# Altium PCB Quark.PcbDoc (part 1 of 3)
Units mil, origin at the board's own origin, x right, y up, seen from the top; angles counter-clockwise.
Board outline 1220.47 x 944.88 mil, 6 copper layers (Top1, Signal2, Gnd3, Power4, Signal5, Bottom6), stack 32.534 mil thick; 106 components, 182 nets, 776 pads, 404 vias.
Unrouted connection lines stored in the file: 82.
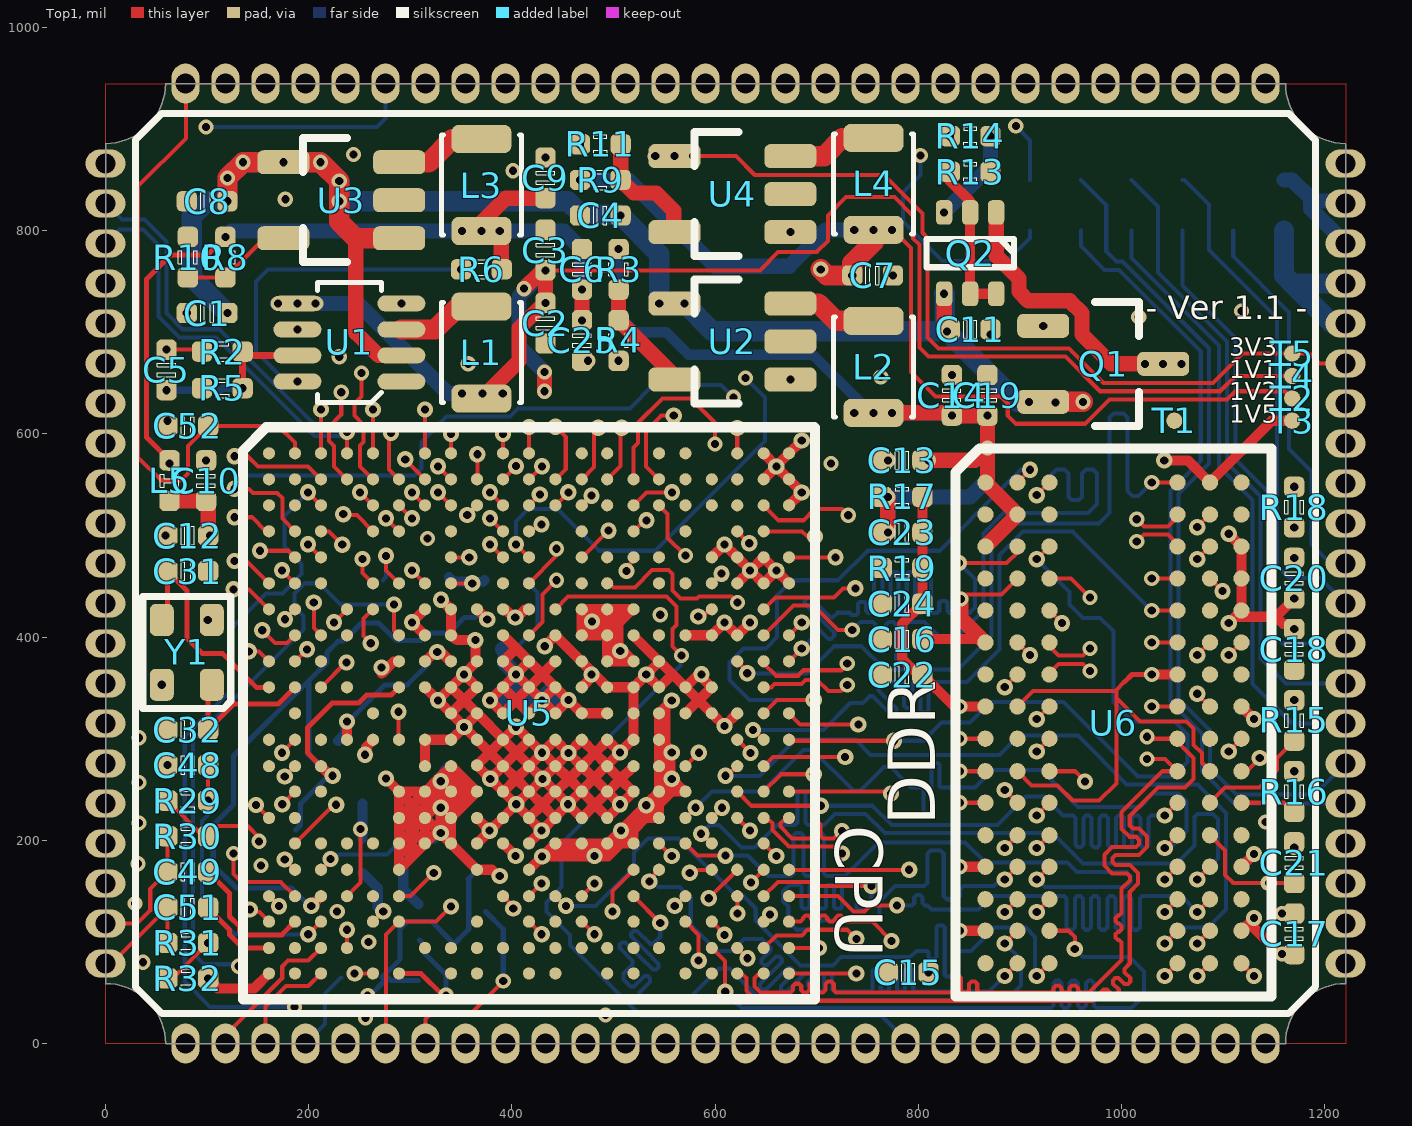
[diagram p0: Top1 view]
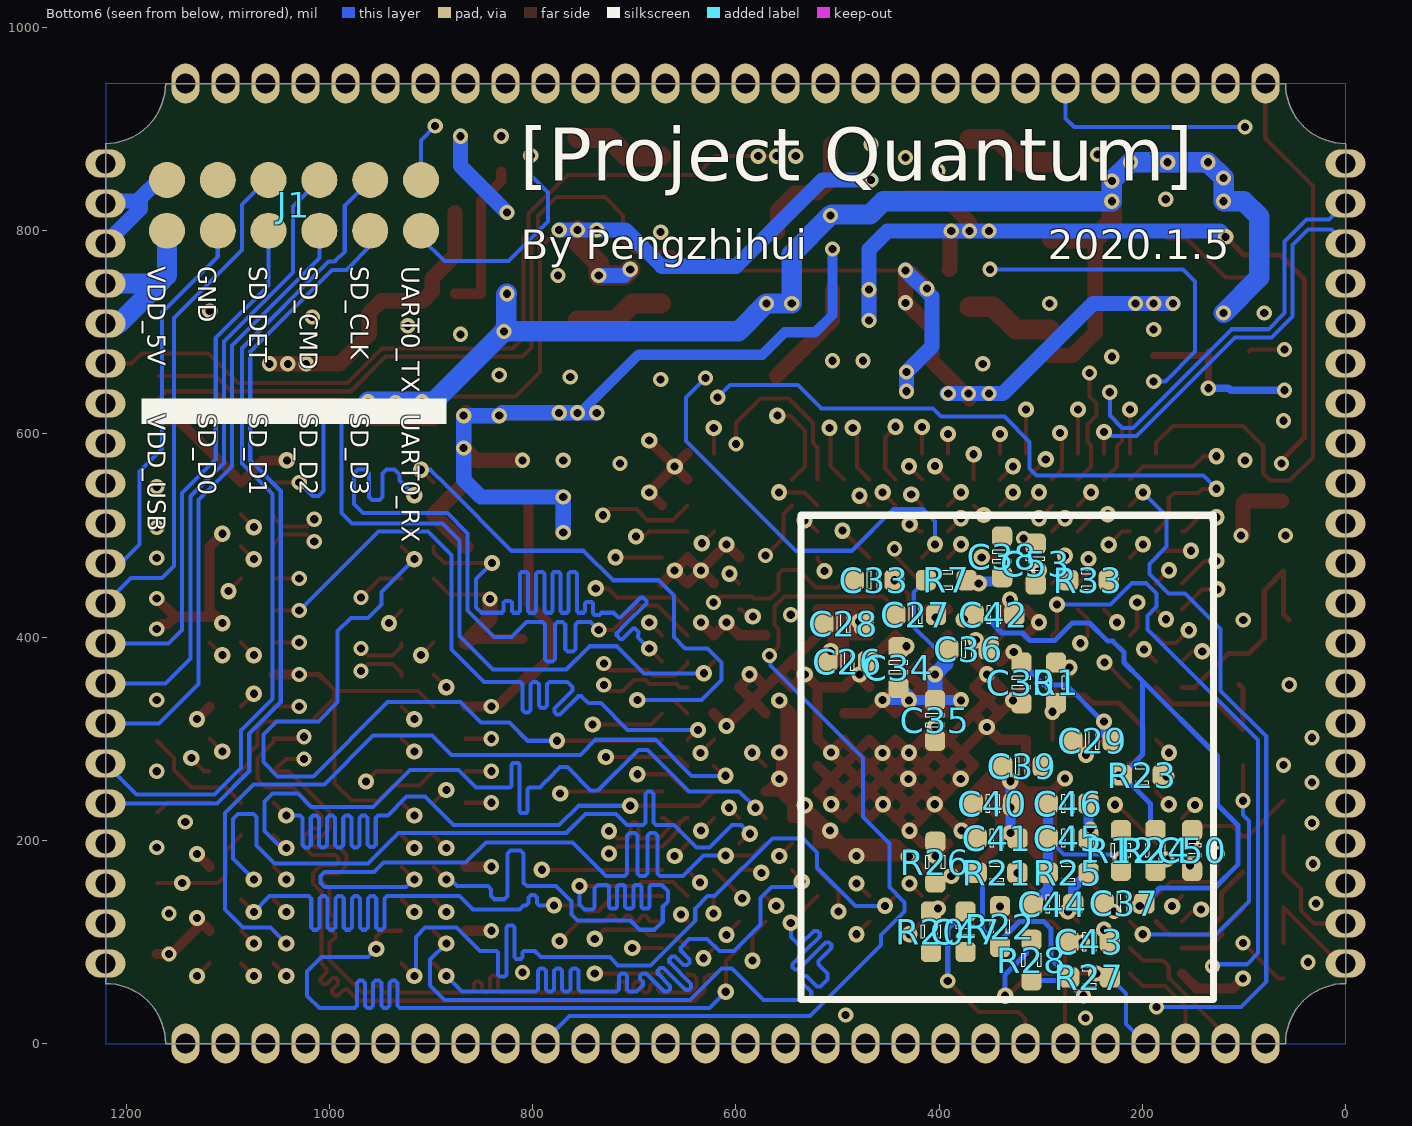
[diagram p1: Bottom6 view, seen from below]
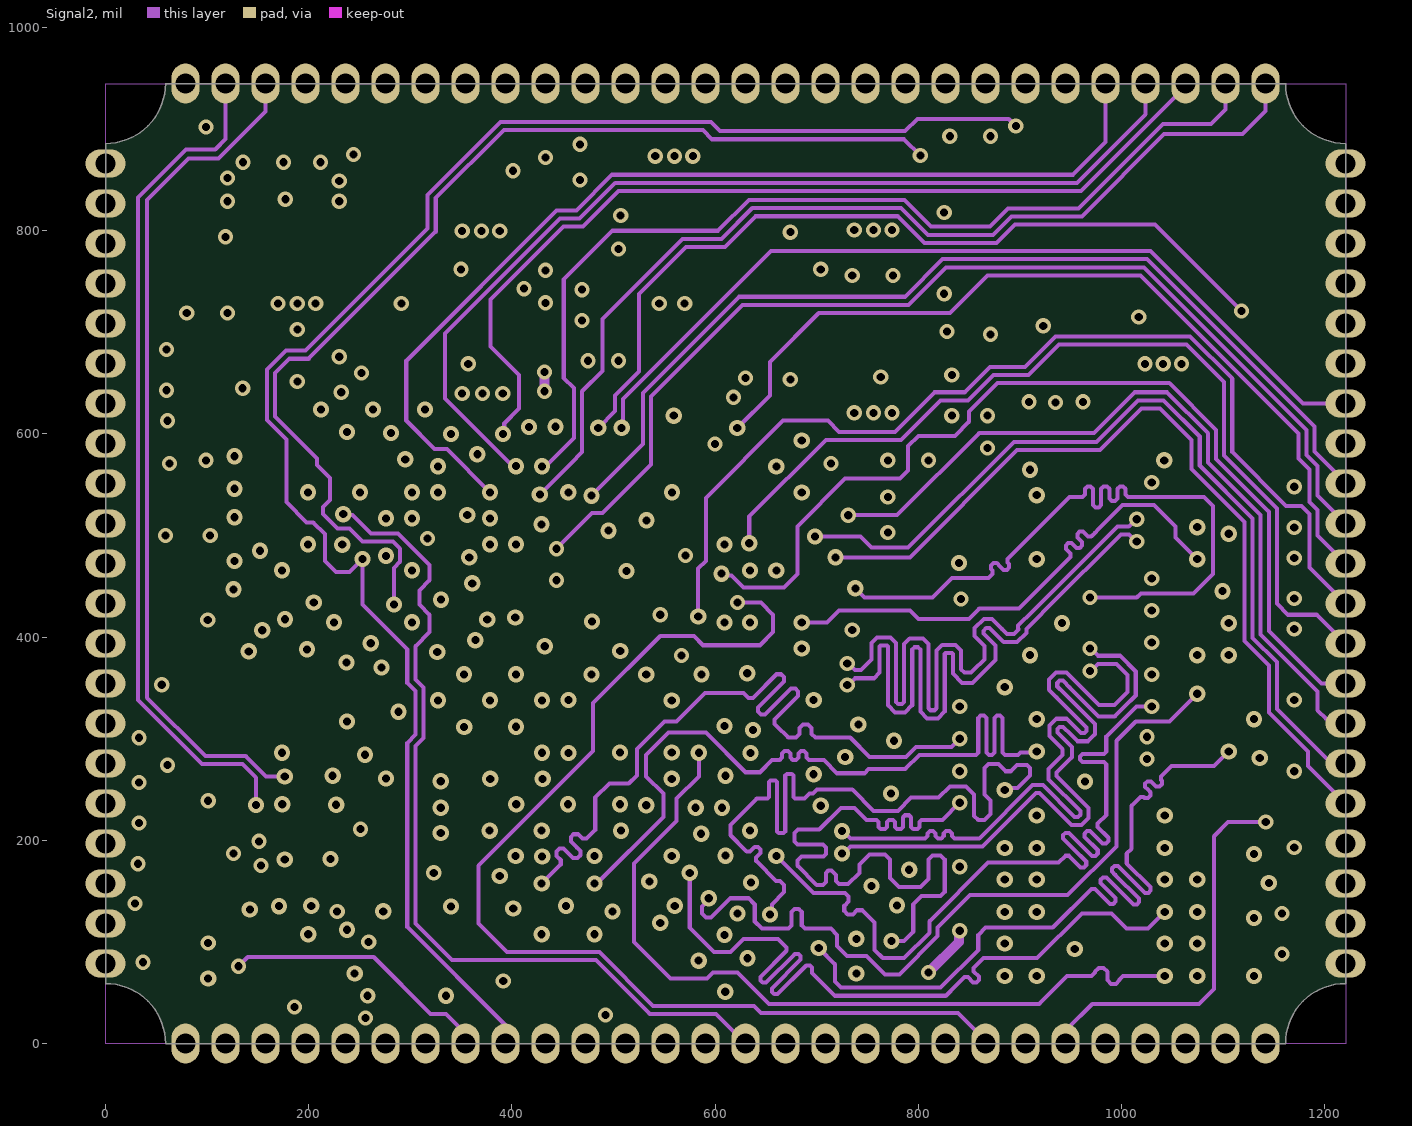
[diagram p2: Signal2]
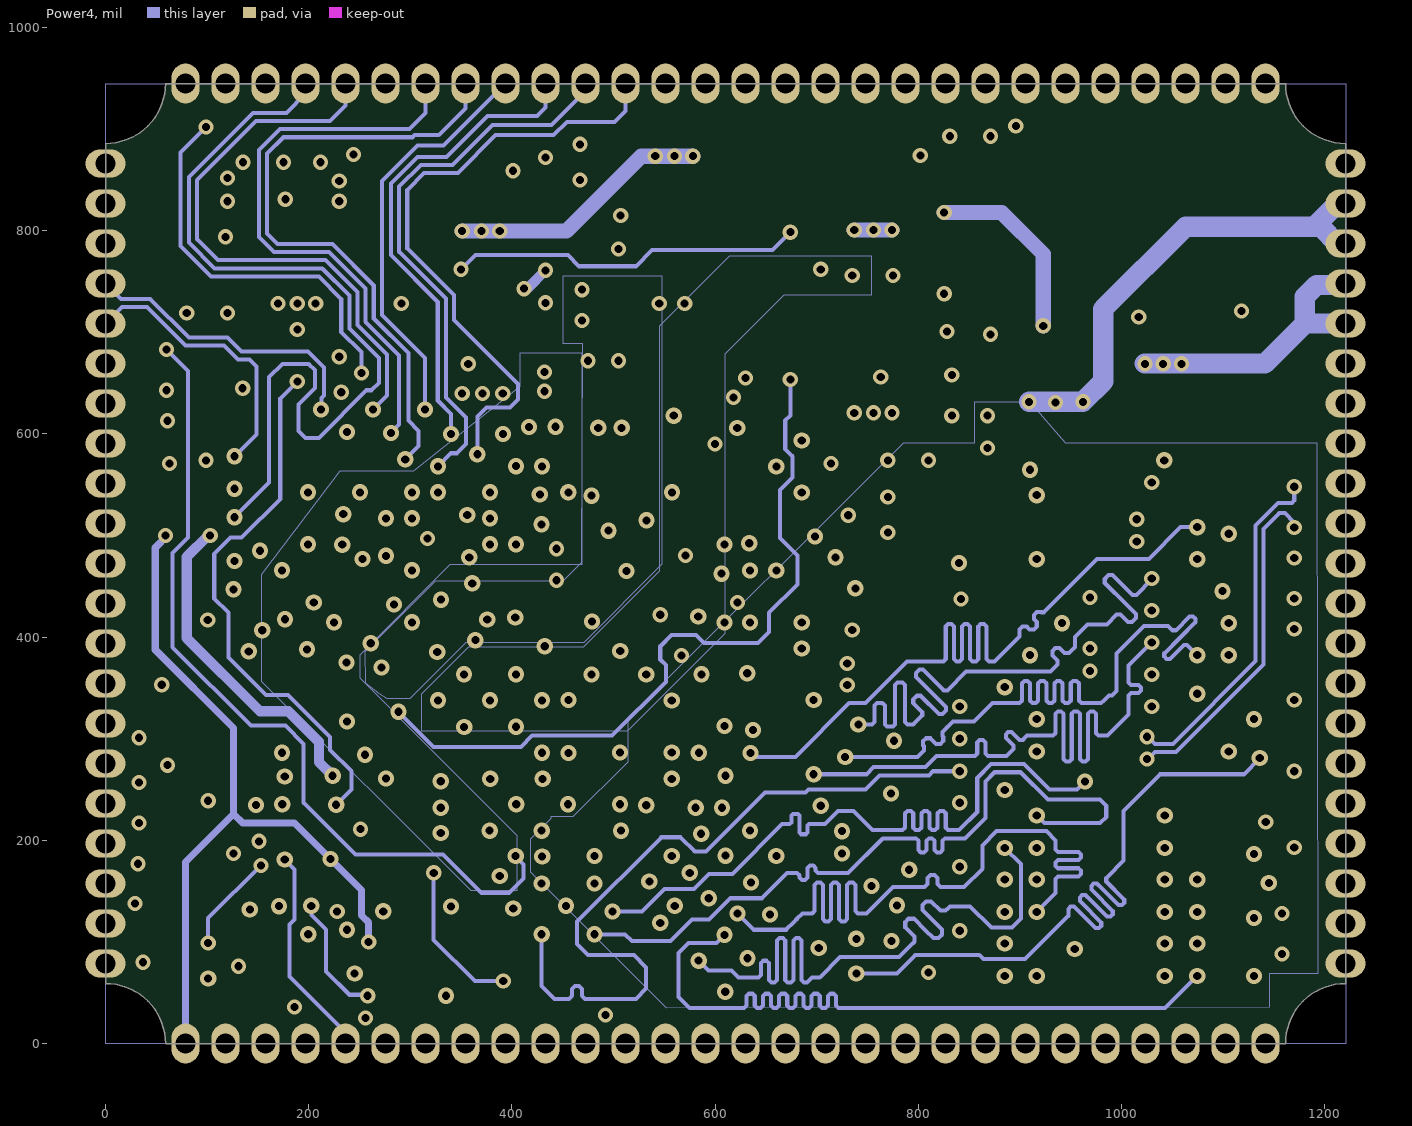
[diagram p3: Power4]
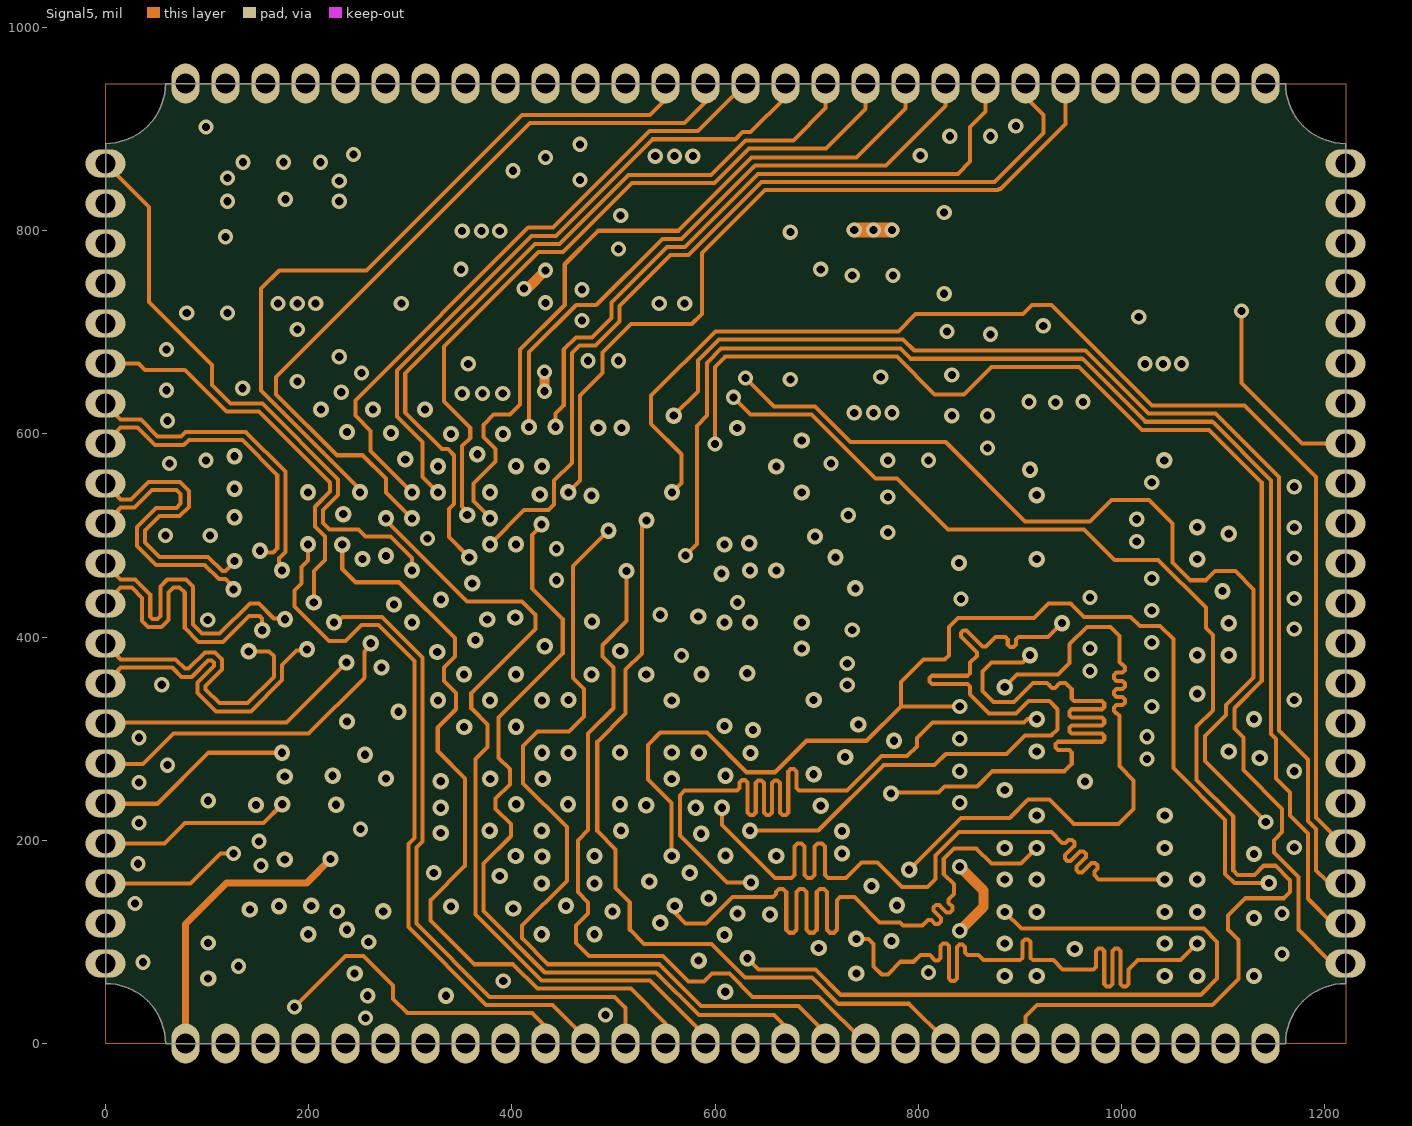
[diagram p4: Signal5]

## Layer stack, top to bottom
Top Solder: solder mask 0.8, Solder Resist, Dk 3.5
Top1: signal copper 1.378
Dielectric1: prepreg 4.2, PP-014, Dk 4.2
Signal2: signal copper 0.689
Dielectric3: core 5, Core-015, Dk 4.4
Gnd3: signal copper 0.689
Dielectric2: prepreg 8.6, PP-023, Dk 4.5
Power4: signal copper 0.689
Dielectric4: core 5, Core-015, Dk 4.4
Signal5: signal copper 0.689
Dielectric5: prepreg 4.2, PP-014, Dk 4.2
Bottom6: signal copper 1.4
Bottom Solder: solder mask 0.8, Solder Resist, Dk 3.5

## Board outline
0,59.06 0,885.83 ccw(c0,944.88) 59.06,944.88 1161.42,944.88 ccw(c1220.47,944.88) 1220.47,885.83 1220.47,59.06 ccw(c1220.47,0) 1161.42,0 59.06,0 ccw(c0,0)

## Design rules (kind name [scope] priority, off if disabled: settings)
AssemblyTestPointUsage [All] p0: scope1count=1 scope1_0_kind=Board scope1_0_value=Board scope2count=1 scope2_0_kind=Board scope2_0_value=Board commentlength=0
AssemblyTestpoint [All] p0: scope1count=1 scope1_0_kind=Board scope1_0_value=Board scope2count=1 scope2_0_kind=Board scope2_0_value=Board commentlength=0
Clearance [All] p0: scope1count=1 scope1_0_kind=Board scope1_0_value=Board scope2count=1 scope2_0_kind=Board scope2_0_value=Board commentlength=0 gap=4
Clearance [All] p1: gap=4 ignorepadtopadclearanceinfootprint=FALSE except(0: Arc-Hole Track-Hole SMDPad-Hole THPad-Hole Via-Hole Fill-Hole Poly-Hole Region-Hole Text-Hole)
ComponentClearance [All] p0: scope1count=1 scope1_0_kind=Board scope1_0_value=Board scope2count=1 scope2_0_kind=Board scope2_0_value=Board commentlength=0 gap=0 collisioncheckmode=3
ComponentClearance [All] p1: gap=0 collisioncheckmode=3 verticalgap=0 showdistances=FALSE
DiffPairsRouting [All] p0: scope1count=1 scope1_0_kind=Board scope1_0_value=Board scope2count=1 scope2_0_kind=Board scope2_0_value=Board commentlength=0
DiffPairsRouting [All] p1: maxlimit=4 minlimit=4 mostfreqgap=4 toplayer_minwidth=4 toplayer_maxwidth=4 toplayer_prefwidth=4 midlayer1_minwidth=4 midlayer1_maxwidth=4 midlayer1_prefwidth=4 midlayer2_minwidth=4 midlayer2_maxwidth=4 midlayer2_prefwidth=4 midlayer3_minwidth=4 midlayer3_maxwidth=4 midlayer3_prefwidth=4 midlayer4_minwidth=4 midlayer4_maxwidth=4 midlayer4_prefwidth=4 bottomlayer_minwidth=4 bottomlayer_maxwidth=4 bottomlayer_prefwidth=4 maxuncoupledlength=500
FabricationTestPointUsage [All] p0: scope1count=1 scope1_0_kind=Board scope1_0_value=Board scope2count=1 scope2_0_kind=Board scope2_0_value=Board commentlength=0 valid=0 allowmultiple=FALSE
FabricationTestpoint [All] p0: scope1count=1 scope1_0_kind=Board scope1_0_value=Board scope2count=1 scope2_0_kind=Board scope2_0_value=Board commentlength=0 side=3 testpointundercomponent=TRUE minsize=40 maxsize=100 preferedsize=60 minholesize=0 maxholesize=40 preferedholesize=32 testpointgrid=1
FanoutControl Fanout_Default [All] p0: scope1count=1 scope1_0_kind=Board scope1_0_value=Board scope2count=1 scope2_0_kind=Board scope2_0_value=Board commentlength=30 // Fanout_Default (Default Rule)
FanoutControl Fanout_Small [All] p0 off: scope1count=1 scope1_0_kind=Board scope1_0_value=Board scope2count=1 scope2_0_kind=Board scope2_0_value=Board commentlength=84 // Protel DXP Scope 1 Expression Was: (CompPinCount < 5)   Fanout_Small (Default Rule)
FanoutControl Fanout_SOIC [All] p0 off: scope1count=1 scope1_0_kind=Board scope1_0_value=Board scope2count=1 scope2_0_kind=Board scope2_0_value=Board commentlength=71 // Protel DXP Scope 1 Expression Was: IsSOIC   Fanout_SOIC (Default Rule)
FanoutControl Fanout_LCC [All] p0 off: scope1count=1 scope1_0_kind=Board scope1_0_value=Board scope2count=1 scope2_0_kind=Board scope2_0_value=Board commentlength=69 // Protel DXP Scope 1 Expression Was: IsLCC   Fanout_LCC (Default Rule)
FanoutControl Fanout_BGA [All] p0: scope1count=1 scope1_0_kind=Board scope1_0_value=Board scope2count=1 scope2_0_kind=Board scope2_0_value=Board commentlength=26 // Fanout_BGA (Default Rule)
FanoutControl Fanout_BGA [All] p1: bgadir=Out bgaviamode=Centered fanoutstyle=Auto fanoutdirection=Alternating viagrid=1 // Fanout_BGA (Default Rule)
Height [All] p0: scope1count=1 scope1_0_kind=Board scope1_0_value=Board scope2count=1 scope2_0_kind=Board scope2_0_value=Board commentlength=0
HoleSize [All] p0: scope1count=1 scope1_0_kind=Board scope1_0_value=Board scope2count=1 scope2_0_kind=Board scope2_0_value=Board commentlength=0 absolutevalues=TRUE maxlimit=10000 minlimit=8 maxpercent=80.000 minpercent=20.000
HoleSize [All] p1: absolutevalues=TRUE maxlimit=10000 minlimit=8 maxpercent=80.000 minpercent=20.000
HoleToHoleClearance [All] p0: scope1count=1 scope1_0_kind=Board scope1_0_value=Board scope2count=1 scope2_0_kind=Board scope2_0_value=Board commentlength=0
LayerPairs [All] p0: scope1count=1 scope1_0_kind=Board scope1_0_value=Board scope2count=1 scope2_0_kind=Board scope2_0_value=Board commentlength=0 enforce=TRUE
MinimumSolderMaskSliver [All] p0 off: scope1count=1 scope1_0_kind=Board scope1_0_value=Board scope2count=1 scope2_0_kind=Board scope2_0_value=Board commentlength=0
MinimumSolderMaskSliver [All] p1 off: minsoldermaskwidth=2
NetAntennae [All] p0: scope1count=1 scope1_0_kind=Board scope1_0_value=Board scope2count=1 scope2_0_kind=Board scope2_0_value=Board commentlength=0
PasteMaskExpansion [All] p0: scope1count=1 scope1_0_kind=Board scope1_0_value=Board scope2count=1 scope2_0_kind=Board scope2_0_value=Board commentlength=0 expansion=0
PlaneClearance [All] p0: scope1count=1 scope1_0_kind=Board scope1_0_value=Board scope2count=1 scope2_0_kind=Board scope2_0_value=Board commentlength=0 clearance=8
PlaneClearance [All] p1: clearance=8
PlaneConnect [All] p0: scope1count=1 scope1_0_kind=Board scope1_0_value=Board scope2count=1 scope2_0_kind=Board scope2_0_value=Board commentlength=0 planeconnectstyle=Direct reliefexpansion=20 reliefentries=4 reliefconductorwidth=10 reliefairgap=10
PlaneConnect [All] p1: planeconnectstyle=Direct reliefexpansion=20 reliefentries=4 reliefconductorwidth=10 reliefairgap=10
PolygonConnect [All] p0: scope1count=1 scope1_0_kind=Board scope1_0_value=Board scope2count=1 scope2_0_kind=Board scope2_0_value=Board commentlength=0 connectstyle=Direct reliefconductorwidth=10 reliefentries=4 polygonreliefangle="90 Angle"
PolygonConnect [All] p1: connectstyle=Direct reliefconductorwidth=10 reliefentries=4 polygonreliefangle="90 Angle" airgapwidth=10
RoutingCorners [All] p0: scope1count=1 scope1_0_kind=Board scope1_0_value=Board scope2count=1 scope2_0_kind=Board scope2_0_value=Board commentlength=0 cornerstyle=45-Degree minsetback=100 maxsetback=100
RoutingLayers [All] p0: scope1count=1 scope1_0_kind=Board scope1_0_value=Board scope2count=1 scope2_0_kind=Board scope2_0_value=Board commentlength=0 top layer=Automatic mid layer 1=Automatic mid layer 2=Automatic mid layer 3=Automatic mid layer 4=Automatic bottom layer=Automatic
RoutingPriority [All] p0: scope1count=1 scope1_0_kind=Board scope1_0_value=Board scope2count=1 scope2_0_kind=Board scope2_0_value=Board commentlength=0
RoutingTopology [All] p0: scope1count=1 scope1_0_kind=Board scope1_0_value=Board scope2count=1 scope2_0_kind=Board scope2_0_value=Board commentlength=0 topology=Shortest
RoutingVias [All] p0: scope1count=1 scope1_0_kind=Board scope1_0_value=Board scope2count=1 scope2_0_kind=Board scope2_0_value=Board commentlength=0 holewidth=8 width=16 viastyle="Through Hole" minholewidth=6 minwidth=12 maxholewidth=28 maxwidth=50
RoutingVias [All] p1: holewidth=8 width=16 viastyle="Through Hole" minholewidth=6 minwidth=12 maxholewidth=28 maxwidth=50
ShortCircuit [All] p0: scope1count=1 scope1_0_kind=Board scope1_0_value=Board scope2count=1 scope2_0_kind=Board scope2_0_value=Board commentlength=0 allowed=FALSE
SilkToBoardRegionClearance [All] p0: scope1count=1 scope1_0_kind=Board scope1_0_value=Board scope2count=1 scope2_0_kind=Board scope2_0_value=Board commentlength=0
SilkToSilkClearance [All] p0: scope1count=1 scope1_0_kind=Board scope1_0_value=Board scope2count=1 scope2_0_kind=Board scope2_0_value=Board commentlength=0
SilkToSilkClearance [All] p1: silktosilkclearance=0
SilkToSolderMaskClearance [All] p0 off: scope1count=1 scope1_0_kind=Board scope1_0_value=Board scope2count=1 scope2_0_kind=Board scope2_0_value=Board commentlength=44 // Protel DXP Scope 1 Expression Was: IsPad
SilkToSolderMaskClearance [IsPad] p1: minsilkscreentomaskgap=0 clearancetoexposedcopper=TRUE
SolderMaskExpansion [All] p0: scope1count=1 scope1_0_kind=Board scope1_0_value=Board scope2count=1 scope2_0_kind=Board scope2_0_value=Board commentlength=0 expansion=3
SolderMaskExpansion [All] p1: expansion=3 istentingtop=FALSE
UnRoutedNet [All] p0: scope1count=1 scope1_0_kind=Board scope1_0_value=Board scope2count=1 scope2_0_kind=Board scope2_0_value=Board commentlength=0
UnpouredPolygon [All] p0: scope1count=1 scope1_0_kind=Board scope1_0_value=Board scope2count=1 scope2_0_kind=Board scope2_0_value=Board commentlength=0
Width [All] p0: scope1count=1 scope1_0_kind=Board scope1_0_value=Board scope2count=1 scope2_0_kind=Board scope2_0_value=Board commentlength=0 maxlimit=10000 minlimit=4 preferedwidth=4
Width GND [All] p0 off: scope1count=1 scope1_0_kind=Board scope1_0_value=Board scope2count=1 scope2_0_kind=Board scope2_0_value=Board commentlength=70 maxlimit=50 minlimit=4 preferedwidth=10 // Protel DXP Scope 1 Expression Was: (InNet('AGND') OR InNet('GND'))
Width VCC [All] p0 off: scope1count=1 scope1_0_kind=Board scope1_0_value=Board scope2count=1 scope2_0_kind=Board scope2_0_value=Board commentlength=237 maxlimit=50 minlimit=4 preferedwidth=10 // Protel DXP Scope 1 Expression Was: (InNet('VDD_SYS_3.3V') OR InNet('VDD_AV_3.3V') OR InNet('VDD_5V') OR InNet('VDD1V2-SYS') OR InNet('VDD1V1-EPHY') OR InNet('VDD-CPUX') OR InNet('VDD-CPUS') OR InNet('VDD-CPUFB') OR InNet('VCC-DRAM'))
Width GND [(InNet('AGND') OR InNet('GND'))] p1: maxlimit=50 minlimit=4 preferedwidth=10
Width VCC [(InNet('VDD_SYS_3.3V') OR InNet('VDD_AV_3.3V') OR InNet('VDD_5V') OR InNet('VDD1V2-SYS') OR InNet('VDD1V1-EPHY') OR InNet('VDD-CPUX') OR InNet('VDD-CPUS') OR InNet('VDD-CPUFB') OR InNet('VCC-DRAM'))] p2: maxlimit=50 minlimit=4 preferedwidth=10
Width [All] p3: maxlimit=10000 minlimit=4 preferedwidth=4
21 further rules are at their usual default settings.

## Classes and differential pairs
component class Power: C1 C2 C3 C4 C5 C6 C7 C8 C9 C10 C11 C12 L1 L2 L3 L4 L5 Q1 Q2 R1 R2 R3 R4 R5 R6 R7 R8 R9 R10 R11 R12 R13 R14 T1 T2 T3 T4 T5 U1 U2 U3 U4
component class CPU&DRAM: C13 C14 C15 C16 C17 C18 C19 C20 C21 C22 C23 C24 C25 C26 C27 C28 C29 C30 C31 C32 C33 C34 C35 C36 C37 C38 C39 C40 C41 C42 C43 C44 C45 C46 C47 C48 C49 C50 C51 C52 C53 R15 R16 R17 R18 R19 R20 R21 R22 R23 R24 R25 R26 R27 R28 R29 R30 R31 R32 R33 R43 U5 U6 Y1
component class Connect: J1
differential pair SDQS0: +SDQS0_P -SDQS0_N
differential pair SDQS1: +SDQS1_P -SDQS1_N
differential pair SCK: +SCK_P -SCK_N
differential pair HTX0: +HTX0_P -HTX0_N
differential pair HTX1: +HTX1_P -HTX1_N
differential pair HTX2: +HTX2_P -HTX2_N
differential pair " ": +HTXC_P -HTXC_N

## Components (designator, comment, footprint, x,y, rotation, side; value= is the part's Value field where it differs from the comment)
C1 "10uF" CAP_0402 100,719 r0 top
C2 "10uF" CAP_0402 433,709 r90 top
C3 "0.1uF" CAP_0402 433,781 r270 top
C4 "10uF" CAP_0402 487,815 r0 top
C5 "10uF" CAP_0402 60,663 r90 top
C6 "10uF" CAP_0402 469,762 r270 top
C7 "10uF" CAP_0402 755,756 r180 top
C8 "10uF" CAP_0402 100,829 r0 top
C9 "10uF" CAP_0402 433,852 r270 top
C10 "10uF" CAP_0402 99,554 r270 top
C11 "10uF" CAP_0402 851,703 r180 top
C12 "10uF" CAP_0402 81,500 r0 top
C13 "10uF" CAP_0402 784,574 r0 top
C14 "1uF" CAP_0402 833,638 r270 top
C15 "0.1uF" CAP_0402 790,70 r0 top
C16 "0.1uF" CAP_0402 784,398 r0 top
C17 "0.1uF" CAP_0402 1170,108 r270 top
C18 "0.1uF" CAP_0402 1170,388 r90 top
C19 "0.1uF" CAP_0402 868,638 r270 top
C20 "0.1uF" CAP_0402 1170,458 r270 top
C21 "0.1uF" CAP_0402 1170,178 r270 top
C22 "0.1uF" CAP_0402 784,363 r0 top
C23 "0.1uF" CAP_0402 784,503 r180 top
C24 "0.1uF" CAP_0402 784,433 r0 top
C25 "0.1uF" CAP_0402 469,692 r90 top
C26 "0.1uF" CAP_0402 490,376 r0 bottom
C27 "0.1uF" CAP_0402 423,422 r180 bottom
C28 "0.1uF" CAP_0402 494,413 r180 bottom
C29 "1uF" CAP_0402 249,298 r180 bottom
C30 "0.1uF" CAP_0402 319,355 r90 bottom
C31 "18pF" CAP_0402 81,465 r0 top
C32 "18pF" CAP_0402 81,309 r0 top
C33 "10uF" CAP_0402 464,456 r0 bottom
C34 "0.1uF" CAP_0402 440,370 r270 bottom
C35 "0.1uF" CAP_0402 404,318 r90 bottom
C36 "0.1uF" CAP_0402 371,388 r0 bottom
C37 "0.1uF" CAP_0402 218,138 r0 bottom
C38 "0.1uF" CAP_0402 338,479 r270 bottom
C39 "10uF" CAP_0402 318,273 r0 bottom
C40 "0.1uF" CAP_0402 347,236 r180 bottom
C41 "0.1uF" CAP_0402 343,202 r180 bottom
C42 "0.1uF" CAP_0402 346,422 r0 bottom
C43 "1uF" CAP_0402 252,100 r0 bottom
C44 "10uF" CAP_0402 288,137 r180 bottom
C45 "10uF" CAP_0402 273,202 r180 bottom
C46 "0.1uF" CAP_0402 273,236 r180 bottom
C47 "0.1uF" CAP_0402 374,110 r90 bottom
C48 "1uF" CAP_0402 81,274 r180 top
C49 "0.1uF" CAP_0402 81,169 r180 top
C50 "10uF" CAP_0402 151,190 r90 bottom
C51 "0.1uF" CAP_0402 81,134 r180 top
C52 "0.1uF" CAP_0402 81,608 r0 top
C53 "0.1uF" CAP_0402 305,472 r270 bottom
J1 "MIPI0" TEST_CORE 910,800 r0 bottom
L1 "2.2uH" 2520-L 370,680 r270 top
L2 "2.2uH" 2520-L 756,666 r270 top
L3 "2.2uH" 2520-L 370,845 r270 top
L4 "2.2uH" 2520-L 756,846 r270 top
L5 "H0402" IND_0402 63,554 r270 top
Q1 "AO3415A" SOT23-3 982,669 r0 top
Q2 "BCM856BS" SOT363-6 851,778 r270 top
R1 "10K" RES_0402 285,355 r90 bottom
R2 "10K/1%" RES_0402 115,681 r180 top
R3 "15K/1%" RES_0402 505,762 r270 top
R4 "10K/1%" RES_0402 505,692 r90 top
R5 "12K/1%" RES_0402 115,645 r0 top
R6 "10K" RES_0402 370,762 r0 top
R7 "2R/1%" RES_0402 393,456 r180 bottom
R8 "30K/1%" RES_0402 118,774 r270 top
R9 "10K/1%" RES_0402 487,850 r180 top
R10 "6.8K/1%" RES_0402 81,774 r270 top
R11 "10K/1%" RES_0402 487,885 r0 top
R12 "0R" RES_0402 221,190 r90 bottom
R13 "10K/1%" RES_0402 851,858 r180 top
R14 "10K/1%" RES_0402 851,893 r180 top
R15 "240R/1%" RES_0402 1170,318 r90 top
R16 "240R/1%" RES_0402 1170,248 r90 top
R17 "2K/1%" RES_0402 784,538 r180 top
R18 "100R" RES_0402 1170,528 r90 top
R19 "2K/1%" RES_0402 784,468 r0 top
R20 "240R/1%" RES_0402 408,110 r270 bottom
R21 "1M" RES_0402 343,168 r0 bottom
R22 "10K" RES_0402 340,115 r270 bottom
R23 "47K" RES_0402 200,264 r0 bottom
R24 "10K" RES_0402 187,190 r90 bottom
R25 "220K/1%" RES_0402 273,168 r180 bottom
R26 "0R" RES_0402 403.68,178.5 r270 bottom
R27 "100K" RES_0402 252,65 r180 bottom
R28 "47K" RES_0402 309,82 r90 bottom
R29 "1K" RES_0402 81,239 r0 top
R30 "2K" RES_0402 81,204 r0 top
R31 "2K" RES_0402 81,99 r180 top
R32 "1K" RES_0402 81,64 r180 top
R33 "6K/1%" RES_0402 253,456 r0 bottom
T1 "测试点" TEST_PT 1052,613 r0 top
T2 "测试点" TEST_PT 1168.01,635 r90 top
T3 "测试点" TEST_PT 1168.01,613 r90 top
T4 "测试点" TEST_PT 1168.01,657 r90 top
T5 "测试点" TEST_PT 1168.01,679 r90 top
U1 "MP2143DJ" SOT23-8 240,690 r90 top
U2 "RT8059" SOT23-5 615,691 r180 top
U3 "RT8059" SOT23-5 230,830 r180 top
U4 "SY8089A" SOT23-5 615,836 r180 top
U5 "ALLWINNER-H3(FBGA-347)" "FBGA-347 - duplicate" 416.77,325 r0 top locked
U6 "K4B4G1646D-BCK0(FBGA-96_256Mx16_DDR3-1600_11-11-11)" FBGA96(HYNIX_SAMSUNG_512MX16_DDR3) 992,316 r270 top locked
Y1 "24MHz" 晶振2520 80,385 r90 top

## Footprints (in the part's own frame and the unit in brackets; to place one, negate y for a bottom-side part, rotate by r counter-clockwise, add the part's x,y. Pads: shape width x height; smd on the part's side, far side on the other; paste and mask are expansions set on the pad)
2520-L [mm]
  rrect50% 0.7x1.5 smd: 1(-1.15,0) 2(1.15,0)
  silkscreen extent -1.25,-1 1.25,1
CAP_0402 [mil]
  rrect50% 20x20 smd: 1(-20,0) 2(20,0)
  silkscreen extent -6,-9 6,9
FBGA96(HYNIX_SAMSUNG_512MX16_DDR3) [mil] "FBGA96(HYNIX_SAMSUNG_512MX16_DDR3)"
  rrect100% 16x16 smd: A1(-236.22,-125.98) A2(-236.22,-94.49) A3(-236.22,-62.99) A7(-236.22,63) A8(-236.22,95) A9(-236.22,126) B1(-204.72,-125.98) B2(-204.72,-94.49) B3(-204.72,-62.99) B7(-204.72,63) B8(-204.72,95) B9(-204.72,126) C1(-173.23,-125.98) C2(-173.23,-94.49) C3(-173.23,-62.99) C7(-173.23,63) C8(-173.23,95) C9(-173.23,126) D1(-141.73,-125.98) D2(-141.73,-94.49) D3(-141.73,-62.99) D7(-141.73,63) D8(-141.73,95) D9(-141.73,126) E1(-110.24,-125.98) E2(-110.24,-94.49) E3(-110.24,-62.99) E7(-110.24,63) E8(-110.24,95) E9(-110.24,126) F1(-78.74,-125.98) F2(-78.74,-94.49) F3(-78.74,-62.99) F7(-78.74,63) F8(-78.74,95) F9(-78.74,126) G1(-47.24,-125.98) G2(-47.24,-94.49) G3(-47.24,-62.99) G7(-47.24,63) G8(-47.24,95) G9(-47.24,126) H1(-15.75,-125.98) H2(-15.75,-94.49) H3(-15.75,-62.99) H7(-15.75,63) H8(-15.75,95) H9(-15.75,126) J1(16,-125.98) J2(16,-94.49) J3(16,-62.99) J7(16,63) J8(16,95) J9(16,126) K1(48,-125.98) K2(48,-94.49) K3(48,-62.99) K7(48,63) K8(48,95) K9(48,126) L1(79,-125.98) L2(79,-94.49) L3(79,-62.99) L7(79,63) L8(79,95) L9(79,126) M1(111,-125.98) M2(111,-94.49) M3(111,-62.99) M7(111,63) M8(111,95) M9(111,126) N1(142,-125.98) N2(142,-94.49) N3(142,-62.99) N7(142,63) N8(142,95) N9(142,126) P1(174,-125.98) P2(174,-94.49) P3(174,-62.99) P7(174,63) P8(174,95) P9(174,126) R1(205,-125.98) R2(205,-94.49) R3(205,-62.99) R7(205,63) R8(205,95) R9(205,126) T1(237,-125.98) T2(237,-94.49) T3(237,-62.99) T7(237,63) T8(237,95) T9(237,126)
  silkscreen extent -270,-156 270,156
"FBGA-347 - duplicate" [mil] "FBGA-347"
  rrect100% 12x12 smd: A1(-255.91,255.91) A2(-230.31,255.91) A3(-204.72,255.91) A4(-179.13,255.91) A5(-153.54,255.91) A7(-102.36,255.91) A8(-76.77,255.91) A10(-25.59,255.91) A11(0,255.91) A13(52,255.91) A14(77,255.91) A16(128,255.91) A17(154,255.91) A19(205,255.91) A20(231,255.91) A21(256,255.91) AA1(-255.91,-256) AA2(-230.31,-256) AA3(-204.72,-256) AA5(-153.54,-256) AA6(-127.95,-256) AA8(-76.77,-256) AA9(-51.18,-256) AA11(0,-256) AA12(26,-256) AA14(77,-256) AA15(103,-256) AA17(154,-256) AA18(180,-256) AA19(205,-256) AA20(231,-256) AA21(256,-256) B1(-255.91,230.32) B2(-230.31,230.32) B3(-204.72,230.32) B4(-179.13,230.32) B5(-153.54,230.32) B6(-127.95,230.32) B7(-102.36,230.32) B8(-76.77,230.32) B9(-51.18,230.32) B10(-25.59,230.32) B11(0,230.32) B12(26,230.32) B13(52,230.32) B14(77,230.32) B15(103,230.32) B16(128,230.32) B17(154,230.32) B18(180,230.32) B19(205,230.32) B20(231,230.32) B21(256,230.32) C1(-255.91,204.72) C2(-230.31,204.72) C3(-204.72,204.72) C5(-153.54,204.72) C6(-127.95,204.72) C7(-102.36,204.72) C8(-76.77,204.72) C9(-51.18,204.72) C10(-25.59,204.72) C11(0,204.72) C12(26,204.72) C13(52,204.72) C14(77,204.72) C15(103,204.72) C16(128,204.72) C17(154,204.72) C18(180,204.72) C19(205,204.72) C20(231,204.72) C21(256,204.72) D1(-255.91,179.13) D2(-230.31,179.13) D3(-204.72,179.13) D5(-153.54,179.13) D6(-127.95,179.13) D8(-76.77,179.13) D10(-25.59,179.13) D11(0,179.13) D13(52,179.13) D15(103,179.13) D17(154,179.13) D19(205,179.13) D20(231,179.13) E2(-230.31,153.54) E3(-204.72,153.54) E8(-76.77,153.54) E10(-25.59,153.54) E11(0,153.54) E13(52,153.54) E14(77,153.54) E15(103,153.54) E16(128,153.54) E18(180,153.54) E19(205,153.54) E20(231,153.54) E21(256,153.54) F1(-255.91,127.95) F2(-230.31,127.95) F3(-204.72,127.95) F5(-153.54,127.95) F6(-127.95,127.95) F7(-102.36,127.95) F8(-76.77,127.95) F10(-25.59,127.95) F11(0,127.95) F13(52,127.95) F14(77,127.95) F16(128,127.95) F17(154,127.95) F18(180,127.95) F19(205,127.95) F20(231,127.95) F21(256,127.95) G1(-255.91,102.36) G2(-230.31,102.36) G4(-179.13,102.36) G5(-153.54,102.36) G7(-102.36,102.36) G8(-76.77,102.36) G9(-51.18,102.36) G10(-25.59,102.36) G11(0,102.36) G12(26,102.36) G13(52,102.36) G14(77,102.36) G15(103,102.36) G18(180,102.36) G20(231,102.36) H2(-230.31,76.77) H3(-204.72,76.77) H4(-179.13,76.77) H6(-127.95,76.77) H7(-102.36,76.77) H8(-76.77,76.77) H10(-25.59,76.77) H11(0,76.77) H12(26,76.77) H13(52,76.77) H14(77,76.77) H15(103,76.77) H16(128,76.77) H17(154,76.77) H18(180,76.77) H19(205,76.77) H20(231,76.77) H21(256,76.77) J1(-255.91,51.18) J2(-230.31,51.18) J3(-204.72,51.18) J6(-127.95,51.18) J7(-102.36,51.18) J8(-76.77,51.18) J9(-51.18,51.18) J10(-25.59,51.18) J11(0,51.18) J12(26,51.18) J13(52,51.18) J14(77,51.18) J15(103,51.18) J16(128,51.18) J19(205,51.18) J20(231,51.18) J21(256,51.18) K1(-255.91,25.59) K2(-230.31,25.59) K3(-204.72,25.59) K4(-179.13,25.59) K6(-127.95,25.59) K7(-102.36,25.59) K8(-76.77,25.59) K9(-51.18,25.59) K10(-25.59,25.59) K11(0,25.59) K12(26,25.59) K13(52,25.59) K14(77,25.59) K15(103,25.59) K16(128,25.59) K17(154,25.59) K18(180,25.59) K20(231,25.59) L2(-230.31,0) L5(-153.54,0) L8(-76.77,0) L9(-51.18,0) L10(-25.59,0) L11(0,0) L12(26,0) L13(52,0) L14(77,0) L15(103,0) L16(128,0) L17(154,0) L18(180,0) L19(205,0) L20(231,0) L21(256,0) M1(-255.91,-26) M2(-230.31,-26) M3(-204.72,-26) M4(-179.13,-26) M5(-153.54,-26) M6(-127.95,-26) M7(-102.36,-26) M8(-76.77,-26) M9(-51.18,-26) M10(-25.59,-26) M11(0,-26) M12(26,-26) M13(52,-26) M14(77,-26) M15(103,-26) M16(128,-26) M19(205,-26) M20(231,-26) M21(256,-26) N1(-255.91,-52) N2(-230.31,-52) N3(-204.72,-52) N7(-102.36,-52) N8(-76.77,-52) N9(-51.18,-51.18) N10(-25.59,-52) N11(0,-52) N12(26,-52) N13(52,-52) N14(77,-52) N15(103,-52) N16(128,-52) N17(154,-52) N19(205,-52) N20(231,-52) P2(-230.31,-77) P3(-204.72,-77) P6(-127.95,-77) P7(-102.36,-77) P8(-76.77,-77) P9(-51.18,-77) P10(-25.59,-77) P11(0,-77) P12(26,-77) P13(52,-77) P14(77,-77) P15(103,-77) P16(128,-77) P17(154,-77) P19(205,-77) P20(231,-77) P21(256,-77) R1(-255.91,-103) R2(-230.31,-103) R6(-127.95,-103) R7(-102.36,-103) R8(-76.77,-103) R9(-51.18,-103) R10(-25.59,-103) R11(0,-103) R12(26,-103) R13(52,-103) R14(77,-103) R16(128,-103) R17(154,-103) R18(180,-103) R19(205,-103) R20(231,-103) R21(256,-103) T2(-230.31,-128) T3(-204.72,-128) T4(-179.13,-128) T5(-153.54,-128) T6(-127.95,-128) T7(-102.36,-128) T8(-76.77,-128) T9(-51.18,-128) T10(-25.59,-128) T11(0,-128) T12(26,-128) T13(52,-128) T14(77,-128) T15(103,-128) T16(128,-128) T17(154,-128) T18(180,-128) T20(231,-128) U2(-230.31,-154) U3(-204.72,-154) U4(-179.13,-154) U6(-127.95,-154) U9(-51.18,-154) U11(0,-154) U15(103,-154) U16(128,-154) U18(180,-154) U19(205,-154) U20(231,-154) U21(256,-154) V1(-255.91,-180) V2(-230.31,-180) V3(-204.72,-180) V4(-179.13,-180) V5(-153.54,-180) V6(-127.95,-180) V10(-25.59,-180) V11(0,-180) V12(26,-180) V13(52,-180) V15(103,-180) V17(154,-180) V19(205,-180) V20(231,-180) V21(256,-180) W1(-255.91,-205) W2(-230.31,-205) W3(-204.72,-205) W5(-153.54,-205) W6(-127.95,-205) W9(-51.18,-205) W11(0,-205) W12(26,-205) W13(52,-205) W15(103,-205) W17(154,-205) W18(180,-205) W20(231,-205) W21(256,-205) Y1(-255.91,-231) Y2(-230.31,-231) Y3(-204.72,-231) Y4(-179.13,-231) Y7(-102.36,-231) Y8(-76.77,-231) Y9(-51.18,-231) Y10(-25.59,-231) Y11(0,-231) Y12(26,-231) Y13(52,-231) Y14(77,-231) Y15(103,-231) Y16(128,-231) Y17(154,-231) Y18(180,-231) Y19(205,-231) Y20(231,-231) Y21(256,-231)
  silkscreen extent -281,-281 281,281
IND_0402 [mil]
  rrect50% 20x20 smd: 1(-20,0) 2(20,0)
  silkscreen extent -7,-9 7,9
RES_0402 [mil]
  rrect50% 20x20 smd: 1(-20,0) 2(20,0)
  silkscreen extent -7,-10 7,10
SOT23-3 [mm] "SOT23, 3-Leads, Body 3.1x3.0mm (max), Pitch 0.95mm, IPC Medium Density"
  rrect50% 1.3x0.6 smd: 1(-1.5,0.95) 2(-1.5,-0.95) 3(1.5,0)
  silkscreen extent -0.2,-1.55 0.9,1.55
SOT23-5 [mm] "SOT23, 3-Leads, Body 3.1x3.0mm (max), Pitch 0.95mm, IPC Medium Density"
  rrect50% 1.3x0.6 smd: 1(-1.5,0.95) 2(-1.5,0) 3(-1.5,-0.95) 4(1.396,-0.95) 5(1.396,0.95)
  silkscreen extent -0.2,-1.55 0.9,1.55
SOT23-8 [mm]
  oval 0.4x1.2 smd: 1(-0.975,-1.3) 2(-0.325,-1.3) 3(0.325,-1.3) 4(0.975,-1.3) 5(0.975,1.3) 6(0.325,1.3) 7(-0.325,1.3) 8(-0.975,1.3)
  silkscreen extent -1.5,-0.8 1.5,0.8
SOT363-6 [mil]
  rrect50% 24x16 smd: 1(-40,25.59) 2(-40,0) 3(-40,-25.59) 4(40,-25.59) 5(40,0) 6(40,25.59)
  silkscreen extent -14,-43 14,43
TEST_CORE [mm]
  round 0.9 smd: 1(0,0) 2(0,-1.27) 3(1.27,0) 4(1.27,-1.27) 5(2.54,0) 6(2.54,-1.27) 7(3.81,0) 8(3.81,-1.27) 9(5.08,0) 10(5.08,-1.27) 11(6.35,0) 12(6.35,-1.27)
TEST_PT [mil]
  rrect100% 16x16 smd: 0(0,0.01)
晶振2520 [mm]
  rrect50% 0.8x0.6 smd: 1(-0.81,-0.625) 2(0.81,-0.625) 3(0.81,0.625) 4(-0.81,0.625)
  silkscreen extent -1.4,-1.1 1.4,1.1

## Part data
C1 C2 C3 C4 C5 C6 C7 C8 C9 C10 C11 C12 C13 C14 C15 C16 C17 C18 C19 C20 C21 C22 C23 C24 C25 C26 C27 C28 C29 C30 C31 C32 C33 C34 C35 C36 C37 C38 C39 C40 C41 C42 C43 C44 C45 C46 C47 C48 C49 C50 C51 C52 C53: library part 电容-0402, "Capacitor"
J1: library part TEST_12P
L1 L2 L3 L4: library part 电感-2520, "磁珠"
L5: library part Ind_0402, "Inductor"
Q1: "MOSFET"
Q2: "Transistor"
R1 R2 R3 R4 R5 R6 R7 R8 R9 R10 R11 R12 R13 R14 R15 R16 R17 R18 R19 R20 R21 R22 R23 R24 R25 R26 R27 R28 R29 R30 R31 R32 R33: library part 电阻-0402, "Resistor"
U1 U2 U3 U4: "LDO"
U6: library part K4B8G1646Q-MYK0(FBGA-96_512MX16_DDR3-1600)
Y1: library part 晶振-4Pin-无源, "2520无源"

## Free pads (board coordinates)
  oval 39.37x27.56 hole 19.68: 1(0,866.14) 2(0,826.77) 3(0,787.4) 4(0,748.03) 5(0,708.66) 6(0,669.29) 7(0,629.92) 8(0,590.55) 9(0,551.18) 10(0,511.81) 11(0,472.44) 12(0,433.07) 13(0,393.7) 14(0,354.33) 15(0,314.96) 16(0,275.59) 17(0,236.22) 18(0,196.85) 19(0,157.48) 20(0,118.11) 21(0,78.74) 50(1220.47,78.74) 51(1220.47,118.11) 52(1220.47,157.48) 53(1220.47,196.85) 54(1220.47,236.22) 55(1220.47,275.59) 56(1220.47,314.96) 57(1220.47,354.33) 58(1220.47,393.7) 59(1220.47,433.07) 60(1220.47,472.44) 61(1220.47,511.81) 62(1220.47,551.18) 63(1220.47,590.55) 64(1220.47,629.92) 65(1220.47,669.29) 66(1220.47,708.66) 67(1220.47,748.03) 68(1220.47,787.4) 69(1220.47,826.77) 70(1220.47,866.14)
  oval 27.56x39.37 hole 19.68: 22(78.74,0) 23(118.11,0) 24(157.48,0) 25(196.85,0) 26(236.22,0) 27(275.59,0) 28(314.96,0) 29(354.33,0) 30(393.7,0) 31(433.07,0) 32(472.44,0) 33(511.81,0) 34(551.18,0) 35(590.55,0) 36(629.92,0) 37(669.29,0) 38(708.66,0) 39(748.03,0) 40(787.4,0) 41(826.77,0) 42(866.14,0) 43(905.51,0) 44(944.88,0) 45(984.25,0) 46(1023.62,0) 47(1062.99,0) 48(1102.36,0) 49(1141.73,0) 71(1141.73,944.88) 72(1102.36,944.88) 73(1062.99,944.88) 74(1023.62,944.88) 75(984.25,944.88) 76(944.88,944.88) 77(905.51,944.88) 78(866.14,944.88) 79(826.77,944.88) 80(787.4,944.88) 81(748.03,944.88) 82(708.66,944.88) 83(669.29,944.88) 84(629.92,944.88) 85(590.55,944.88) 86(551.18,944.88) 87(511.81,944.88) 88(472.44,944.88) 89(433.07,944.88) 90(393.7,944.88) 91(354.33,944.88) 92(314.96,944.88) 93(275.59,944.88) 94(236.22,944.88) 95(196.85,944.88) 96(157.48,944.88) 97(118.11,944.88) 98(78.74,944.88)

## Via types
v1: diameter 16, hole 8, Top1 to Bottom6, tented both sides, 238 vias
v2: diameter 15, hole 8, Top1 to Bottom6, tented both sides, 166 vias

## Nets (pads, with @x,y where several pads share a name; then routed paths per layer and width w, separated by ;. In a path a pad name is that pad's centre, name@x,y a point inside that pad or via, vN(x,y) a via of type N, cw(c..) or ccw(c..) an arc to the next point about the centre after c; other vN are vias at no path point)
AGND: C12.1 C43.2 C44.1 C45.1 C46.1 pad.22 R12.1 R25.1 U5.U3 | length 1257.2
  Top1 w4: U5.U3@212.05,171 v1@224.55,183.5
  Signal5 w7: pad.22@78.74,0 78.74,117.74 119,158 198.05,158 v1(221.55,181.5)
  Power4 w7: v2@61,500 49,488 49,387.57 126,310.57 126,226 ; pad.22@78.74,0 78.74,178.74 126,226 ; v2(259,100) 259,119 252,126 252,151.05 v1(221.55,181.5) 186.05,217 135,217 126,226
  Bottom6 w4: v1(221.55,181.5) 224.79,181.5 229.29,186 277,186 C45.1@293,202
  Bottom6 w10: C46.1@293,236 C45.1@293,202 R25.1@293,168 293,152 C44.1@308,137
  other v2: 59,500
AP-RESET#: C47.2 pad.28 R21.1 U5.V6 | length 386.8
  Top1 w4: U5.V6@288.82,145 300,145 v2(323,168) ; pad.28@314.96,0 314.96,23.96 322,31 361,31 v2(391.5,61.5)
  Power4 w4: v2(323,168) 323,102 363.5,61.5 v2(391.5,61.5)
  Bottom6 w5: C47.2@374,130 391.5,112.5 v2(391.5,61.5)
CAM_D0: pad.81 U5.C9 | length 732.4
  Top1 w4: v1(356,520.13) U5.C9@365.59,529.72
  Signal5 w4: v1(356,520.13) 356,523.38 351,528.38 351,588 359,596 359,606 333,632 333,686 426,779 450.19,779 518.19,847 599.43,847 633.43,881 709,881 748.03,920.03 pad.81@748.03,944.88
CAM_D1: pad.77 U5.E10 | length 872.6
  Top1 w4: v1(378.39,491.34) U5.E10@391.18,478.54
  Signal5 w4: v1(378.39,491.34) 412.05,525 436,525 441.46,530.46 441.46,554 459,571.54 459,679.69 466.31,687 482.31,687 506,710.69 506,726 556,776 573.69,776 609.69,812 644.19,846.5 645.69,848 724.46,848 748.94,848 771.63,848 842.31,848 875,848 923,896 923,914 905.51,931.49 pad.77@905.51,944.88
CAM_D2: pad.80 U5.D10 | length 755
  Top1 w4: v1(378.39,516.93) U5.D10@391.18,504.13
  Signal5 w4: v1(378.39,516.93) 378.39,517.55 362,533.93 362,551 384,573 384,585 372,597 372,609 382,619 398,619 408,629 408,683 452,727 452,767 485,800 563.75,800 599.75,836 635.75,872 739,872 787.4,920.4 pad.80@787.4,944.88
CAM_D3: pad.83 U5.C8 | length 662
  Top1 w4: v1(327.2,542.52) U5.C8@340,529.72
  Signal5 w4: v1(327.2,542.52) 312,557.72 312,592 287,617 287,662.63 419.37,795 443.56,795 538.56,890 619.8,890 625.8,896 626.8,897 635,897 669.29,931.29 pad.83@669.29,944.88
CAM_D4: pad.71 U5.C11 | length 999.6
  Top1 w4: U5.C11@416.77,529.72 v1(427.46,540.41)
  Signal2 w4: v1(427.46,540.41) 458.05,571 ; 458.05,571.05 469,582 469,642 489,662 489,713 568,792 606.31,792 636.54,822.22 783.09,822.22 809.31,796 873.69,796 891.69,814 961,814 1042,895 1070,895 1119,895 1141.73,917.73 pad.71@1141.73,944.88
CAM_D5: pad.76 U5.C12 | length 793.6
  Top1 w4: U5.C12@442.77,529.72 v1(455.57,542.52)
  Signal5 w4: v1(455.57,542.52) 467,553.95 467,638 489,660 489,680 517,708 577,708 587,718 587,778 613,804 649,840 727.77,840 752.25,840 774.94,840 845.63,840 878.31,840 879.31,841 881,841 944.88,904.88 pad.76@944.88,944.88
CAM_D6: pad.82 U5.E8 | length 778.7
  Top1 w4: U5.E8@340,478.54 350.83,478.54 v1(358,478.54)
  Signal5 w4: v1(358,478.54) 338,498.54 338,526 343,531 343,579 337,585 331,585 295,621 295,659.31 422.69,787 446.88,787 513.88,854 514.88,855 596.12,855 627.62,886.5 630.12,889 677,889 708.66,920.66 pad.82@708.66,944.88
CAM_D7: pad.79 U5.A11 | length 632
  Top1 w4: U5.A11@416.77,580.91 v1(416.77,606.91)
  Signal5 w4: v1(416.77,606.91) 416.77,680.46 463.31,727 483,727 548,792 567.06,792 603.06,828 637.56,862.5 639.06,864 717.83,864 742.31,864 768,864 826.77,922.77 pad.79@826.77,944.88
CAM_HSYNC: pad.72 U5.B11 | length 989.2
  Top1 w4: U5.B11@416.77,555.32 v1(429.57,568.11)
  Signal2 w4: v1(429.57,568.11) 433.11,568.11 461,596 461,645 451,655 451,752 499,800 603,800 633.22,830.22 786.4,830.22 812.63,804 870.37,804 888.37,822 957.69,822 1040.69,905 1088,905 1102.36,919.36 pad.72@1102.36,944.88
CAM_MCLK: pad.73 U5.A10 | length 943.3
  Top1 w4: U5.A10@391.18,580.91 v1(391.18,599.91)
  Signal2 w4: v1(391.18,599.91) 392.44,601.17 392.44,610.44 407,625 407,658 379,686 379,732.37 450.63,804 470,804 505,839 891,839 960,839 1062.99,941.99 pad.73@1062.99,944.88
CAM_PCLK: pad.74 U5.B10 | length 988.9
  Top1 w4: U5.B10@391.18,555.32 403.98,568.11 v1(403.98,568.25)
  Signal2 w4: 396.94,572.03 400.73,568.25 v1(403.98,568.25) ; 396.94,572.06 334,635 334,698.69 447.31,812 466.69,812 501.69,847 886,847 956,847 1023.62,914.62 pad.74@1023.62,944.88
CAM_VSYNC: pad.75 U5.C10 | length 1023.7
  Top1 w4: v1(378.39,542.52) U5.C10@391.18,529.72
  Signal2 w4: v1(378.39,542.52) 335.91,585 324,585 296,613 296,672 444,820 463.37,820 498.49,855.12 878.12,855.12 952.12,855.12 984.25,887.25 pad.75@984.25,944.88
EPHY-LINK-LED: C52.2 pad.98 U5.A2 | length 606.7
  Top1 w4: pad.98@79,944.62 79,891 32,844 32,577 55,554 74,554 81,561 81,588 C52.2@101,608 170,608 186.46,591.54 U5.A2@186.46,580.91
EPHY-RXN: pad.3 U5.A4 | length 391.2
  Top1 w4: U5.A4@237.64,580.91 v1(237.64,601.91)
  Bottom6 w4: pad.3@0,787.4 13.6,801 37,801 52,786 52,715.69 72.69,695 108.69,695 205.69,598 230.49,598 234.39,601.91 v1(237.64,601.91)
EPHY-RXP: pad.2 U5.B4 | length 490.8
  Top1 w4: v2(232,641) 232,619 220,607 220,593 224.84,588.16 224.84,568.11 U5.B4@237.64,555.32
  Bottom6 w4: pad.2@0,826.77 0.23,827 16.11,811.11 38.2,811.11 60,789.31 60,719 76,703 112,703 209,606 220,606 232,618 v2(232,641)
EPHY-SPD-LED: C53.2 pad.1 U5.F7 | length 605.5
  Top1 w4: v1(301.61,465.75) U5.F7@314.41,452.95
  Signal5 w4: pad.1@0,866.14 43,823.14 43,730 105,668 105,648 123,630 154.31,630 229,555.31 229,540 214,525 214,512.31 220.31,506 249,506 256,499 280.69,499 301.61,478.07 v1(301.61,465.75)
EPHY-TXN: pad.4 U5.A3 | length 334.9
  Top1 w4: U5.A3@212.05,580.91 U5.A3@212.05,580.91 212,623.95 v1(212.05,624)
  Power4 w4: pad.4@0,748.03 15.03,733 44,733 82,695 120,695 133.81,681.19 199.13,681.19 215,665.31 215,638 212.42,635.42 212.42,624.38 v1(212.05,624)
EPHY-TXP: pad.5 U5.B3 | length 371.3
  Top1 w4: v1(127,578) 140,578 150,568 199.36,568 U5.B3@212.05,555.32
  Power4 w4: pad.5@0,708.66 16.34,725 40.69,725 78.69,687 116.69,687 130.5,673.19 141.81,673.19 148.5,666.5 148.5,599.5 v1(127,578)
GND: C1.1 C2.1 C3.1 C4.1 C6.1 C7.1 C8.1 C9.1 C10.1 C11.1 C13.1 C14.1 C15.1 C16.1 C17.1 C18.1 C19.1 C20.1 C21.1 C22.1 C24.1 C25.1 C26.1 C27.1 C28.1 C29.1 C30.1 C31.2 C32.1 C33.2 C34.1 C35.1 C36.1 C37.2 C38.1 C39.1 C40.1 C41.1 C42.1 C47.1 C48.2 C52.1 C53.1 J1.10 pad.45 pad.46 pad.47 pad.48 pad.49 pad.70 R4.1 R5.1 R10.1 R11.1 R12.2 R13.1 R14.2 R15.2 R16.2 R19.1 R20.2 R32.1 R33.1 T1.0 U1.4 U1.6 U2.2 U3.2 U4.2 U5.A20 U5.A21 U5.AA1 U5.B20 U5.B21 U5.C21 U5.E18 U5.E19 U5.E20 U5.F19 U5.F20 U5.F21 U5.G8 U5.H8 U5.H12 U5.H15 U5.H17 U5.H18 U5.H19 U5.J9 U5.J13 U5.J16 U5.K7 U5.K8 U5.K9 U5.K13 U5.K14 U5.K15 U5.K16 U5.K17 U5.K18 U5.L8 U5.L9 U5.L15 U5.L17 U5.L18 U5.L19 U5.M5 U5.M7 U5.M8 U5.M9 U5.M10 U5.M11 U5.M12 U5.M13 U5.M14 U5.M15 U5.N7 U5.N9 U5.N10 U5.N11 U5.N12 U5.N13 U5.N14 U5.N15 U5.P10 U5.P11 U5.P12 U5.P13 U5.P14 U5.P15 U5.R9 U5.R10 U5.R11 U5.R12 U5.R13 U5.R14 U5.T9 U5.T11 U6.A9 U6.B1 U6.B3 U6.B9 U6.D1 U6.D8 U6.E1 U6.E2 U6.E8 U6.F9 U6.G1 U6.G8 U6.G9 U6.J2 U6.J8 U6.M1 U6.M9 U6.P1 U6.P9 U6.T1 U6.T9 Y1.2 Y1.4 | length 2749.8
  Top1 w4: U6.D8@1087,457.73 v1(1099.5,445.23) ; v1(1105.5,382.24) U6.F9@1118,394.74 ; U6.T9@1118,79 v1(1130.5,66.5)
  Top1 w10: v1(101,64) 111,54 145.87,54 U5.AA1@160.87,69 ; v1(255.43,284.2) 256.58,285.35 256.58,291.81 263.23,298.46 U5.M5@263.23,299 ; U5.N7@314.41,273 U5.M7@314.41,299 U5.M8@340,299 340.41,299 v1(353,311.59) ; U5.K7@314.41,350.59 v1(327.2,337.8) ; v1(330.3,436.86) U5.G8@339.8,427.36 ; U5.K8@340,350.59 352.8,337.8 ; U5.G8@340,427.36 340,402.86 345.86,397 v1(364,397) 364,377.57 U5.J9@365.39,376.18 ; U5.T9@365.59,197 365.77,197 v1@403.98,235.2 ; U5.R9@365.59,222 v1(378.09,209.5) ; U5.J9@365.59,376.18 v1(352.79,363.39) ; U5.L9@365.77,325 U5.M10@391.48,299.3 ; U5.M10@390.77,299 378.18,286.41 ; U5.M10@391.18,299 U5.M10@391.48,299.3 ; U5.P10@391.56,248.38 392.15,248.38 404.27,260.5 ; U5.N10@391.56,272.62 392.15,272.62 404.27,260.5 ; U5.T11@416.77,197 v1(429.27,209.5) ; U5.R11@416.77,222 v1(429.27,209.5) ; U5.P11@416.77,247 U5.P11@417.27,247.5 ; U5.M11@416.77,298.59 404.48,286.3 ; v1(429.57,286.2) U5.M11@416.77,299 v1(403.98,311.8) U5.M10@391.48,299.3 ; v1@430.27,389.07 v1(432.27,391.07) U5.H12@442.77,401.57 ; v1@430.57,286.2 U5.N12@443.27,273.5 ; U5.R12@442.77,222 U5.R12@442.27,222.5 ; U5.H12@442.77,401.77 468.36,376.18 U5.J13@468.77,376.18 468.77,375.82 v1@481.27,363.32 ; 455.27,260.5 U5.N12@442.77,273 ; U5.K13@468.77,350.8 v1@481.27,363.3 ; U5.M14@493.77,299 U5.M14@494.27,298.5 ; v1(506.27,235.5) U5.P14@494.27,247.5 ; U5.P15@519.77,248 U5.P15@519.27,247.5 ; U5.N15@519.77,273 506.77,260 ; U5.H15@519.77,401.77 519.77,401.23 U5.H15@520.77,400.23 ; U5.H15@520.77,400.18 U5.J16@544.77,376.18 ; U5.J16@543.77,374.59 v1(532.27,363.09) ; U5.J16@543.77,374.64 544.77,375.64 U5.J16@544.77,376.18 ; U5.L17@570.77,325 583.57,337.8 ; U5.H17@570.77,401.77 U5.H18@596.77,401.77 v1(609.27,414.27) U5.H19@621.77,401.77 v1(634.27,414.27) ; U5.E18@596.77,478.54 v1(609.27,491.04) U5.E19@621.77,478.54 v1@634.77,465.54 ; U5.L19@621.77,325 v1(609.27,312.5) U5.L18@596.77,325 596.36,325 583.57,337.8 ; U5.F19@621.77,452.95 v1(634.27,465.45) 634.68,465.45 v1@634.77,465.54 ; U5.B20@647.77,555.32 v1(660.27,567.82) ; U5.A20@647.77,580.91 v1@660.27,568.41 ; U5.E20@648.77,476.95 v1(660.27,465.45) ; U5.E20@648.77,477 647.77,478 U5.E20@647.77,478.54 v1@634.77,465.54 ; U5.F21@672.77,452.95 v1(660.27,465.45) ; U5.C21@672.77,529.72 v1(685.27,542.22) 685.27,542.82 U5.B21@672.77,555.32 v1(660.27,567.82) ; v1(685.27,593.41) U5.A21@672.77,580.91 v1@660.27,568.41 ; v1(327.2,337.8) U5.L8@340,325 ; v1(327.2,337.8) v1(352.79,363.39) ; U5.L8@340,325 353,312 v1(353,311.59) ; U5.L8@340,325 352.8,337.8 ; 352.8,337.8 U5.K9@365.59,350.59 v1(352.79,363.39) ; 352.8,337.8 U5.L9@365.59,325 365.59,324.46 364.59,323.46 364.59,323.18 v1(353,311.59) ; v1(353,311.59) U5.M9@365.59,299 378.18,286.41 ; 378.18,286.41 391.18,273.41 U5.N10@391.18,273 ; 378.18,286.41 U5.N9@365.59,273.82 365.59,273.59 v1(378.68,260.5) ; v1(378.68,260.5) U5.N10@391.18,273 ; v1(378.68,260.5) U5.P10@391.18,248 v1@403.98,235.2 ; U5.N10@391.18,273 404.48,286.3 ; U5.M10@391.48,299.3 404.48,286.3 ; v1@403.98,235.2 v1(404.27,235.5) U5.P11@416.77,248 ; v1@403.98,235.2 416.77,222.41 417.18,222.41 429.77,235 ; 404.27,260.5 U5.P11@416.77,248 ; 404.27,260.5 U5.N11@416.77,273 U5.N11@417.27,273.5 ; 404.48,286.3 U5.N11@417.27,273.5 ; U5.P11@416.77,248 U5.P11@417.27,247.5 ; U5.P11@417.27,247.5 429.77,235 ; U5.P11@417.27,247.5 v1(430.27,260.5) ; U5.N11@417.27,273.5 v1(430.27,260.5) ; U5.N11@417.27,273.5 U5.M12@442.77,299 v1(455.77,286) ; v1(429.27,209.5) U5.R12@442.27,222.5 ; 429.77,235 U5.R12@442.27,222.5 ; 429.77,235 U5.P12@442.77,248 ; v1(430.27,260.5) U5.P12@442.77,248 ; v1(430.27,260.5) U5.N12@442.77,273 ; U5.R12@442.27,222.5 v1(455.27,235.5) ; U5.P12@442.77,248 v1(455.27,235.5) ; U5.P12@442.77,248 443.31,248 444.31,249 444.77,249 456.27,260.5 ; U5.N12@442.77,273 U5.N12@443.27,273.5 ; U5.N12@443.27,273.5 v1(455.77,286) ; U5.N12@443.27,273.5 456.27,260.5 ; v1(455.27,235.5) U5.R13@468.77,222 481.77,235 ; v1(455.27,235.5) U5.P13@468.27,248.5 ; v1(455.77,286) U5.M13@468.77,299 481.77,286 ; v1(455.77,286) U5.N13@468.77,273 ; 456.27,260.5 U5.N13@468.77,273 ; 456.27,260.5 U5.P13@468.27,248.5 ; U5.P13@468.27,248.5 U5.P13@468.77,248 481.77,235 ; U5.P13@468.27,248.5 480.77,261 ; U5.N13@468.77,273 481.77,286 ; U5.N13@468.77,273 480.77,261 ; 480.77,261 U5.P14@493.77,248 U5.P14@494.27,247.5 ; 480.77,261 U5.N14@493.54,273.77 ; v1@481.27,363.3 493.77,350.8 U5.K14@493.77,350.59 U5.K15@519.77,350.59 ; 481.77,235 492.77,224 492.77,223.54 493.77,222.54 U5.R14@493.77,222 U5.P15@519.27,247.5 ; 481.77,235 U5.P14@494.27,247.5 ; 481.77,286 492.77,275 492.77,274.54 U5.N14@493.54,273.77 ; 481.77,286 U5.M14@494.27,298.5 ; U5.N14@493.54,273.77 v1(506.27,286.5) ; U5.N14@493.54,273.77 493.77,273.54 U5.N14@493.77,273 506.77,260 ; U5.P14@494.27,247.5 506.77,260 ; U5.M14@494.27,298.5 v1(506.27,286.5) ; v1(506.27,286.5) 517.77,298 518.23,298 519.23,299 U5.M15@519.77,299 U5.L15@519.77,325 U5.K15@519.77,350.59 ; 506.77,260 U5.P15@519.27,247.5 ; U5.K15@519.77,350.59 v1(532.27,363.09) ; v1(532.27,363.09) U5.K16@544.77,350.59 545.18,350.59 557.98,363.39 ; U5.J16@544.77,376.18 545.18,376.18 557.98,363.39 ; 557.98,363.39 U5.K17@570.77,350.59 ; U5.K17@570.77,350.59 583.57,363.39 596.36,350.59 U5.K18@596.77,350.59 583.98,337.8 583.57,337.8 ; U5.K17@570.77,350.59 583.57,337.8 ; v1@634.77,465.54 647.36,452.95 U5.F20@647.77,452.95 v1(660.27,465.45) ; v1(660.27,567.82) v1@660.27,568.41
  other v1: 478.27,363.3 586.57,363.39
  other v2: 256,25 492,28 37,80 1158,128 228,130 29,137.73 32,177 1170,193 33,217 33,257 1170,268 61,274 33,301 1170,338 55.39,353.11 100.61,416.89 546,422 1170,478 317,497 714,571 99,574 770,574 61,613 763,656 833,658 357,669 475,672 505,672 230,676 871,698 188.82,702.8 1017,715 80,719 291.18,728.39 775,756 177,831 401,859 433,872 244,875 467,885 831,893
GPIOA10/STATUS-LED: pad.44 U5.E11 | length 1712.6
  Top1 w4: v1(403.98,491.34) U5.E11@416.77,478.54
  Signal2 w4: pad.44@944.88,0 946.34,1.46 946.34,14.16 971.18,39 1076.18,39 1091,53.82 1091,204 1105,218 v2(1142,218)
  Signal5 w4: v2(630,655) 658,627 698.31,627 733.31,592 827,592 905,514 969,514 990,535 1027,535 1050,512 1050,473.31 1067.31,456 1083,456 1092,465 1112,465 1130,447 1130,360.31 1103,333.31 1103,323.5 1082,302.5 1082,278 v2(1142,218)
  Bottom6 w4: v1(403.98,491.34) 403.98,513.98 416,526 445,526 486,485 541,485 649,593 649,636 v2(630,655)
GPIOE14: pad.85 U5.C6 | length 780.1
  Top1 w4: U5.C6@288.82,529.72 v1(301.61,516.93)
  Signal5 w4: v1(301.61,516.93) 276,542.54 276,556 253,579 227.94,579 168,638.94 168,656 418,906 570,906 590.55,926.55 pad.85@590.55,944.88
GPIOE15: pad.86 U5.C5 | length 749.9
  Top1 w4: v1(250.43,542.52) U5.C5@263.23,529.72
  Signal5 w4: v1(250.43,542.52) 250.43,545.19 153,642.63 153,743 171,761 257,761 410,914 536,914 551.18,929.18 pad.86@551.18,944.88
GPIOG11: pad.43 U5.D2 | length 1943.7
  Top1 w4: v1(127,546) 141,546 145,542 169,542 174,537 174,516.59 U5.D2@186.46,504.13
  Signal5 w4: v2(618,636) 635,619 695,619 758,556 779,556 829,506 963,506 993,476 1036,476 1083,429 1083,409 1090,402 1090,328 1074,312 1074,259.31 1110,223.31 1110,170.31 1114.31,166 1131,166 1140,175 1151.69,175 1166,160.69 1166,149 1160,143 1122,143 1105,126 1105,112 1115,102 1115,63.69 1089.31,38 917,38 905.51,26.51 pad.43@905.51,0
  Bottom6 w4: v1(127,546) 140,559 304,559 311,566 311,592.22 335.78,617 398,617 406,625 516,625 539,648 606,648 v2(618,636)
GPIOG12/USB0-OTGID: pad.95 U5.D1 | length 916.8
  Top1 w4: v1(127,518) 144.31,518 158.17,504.13 U5.D1@160.87,504.13
  Power4 w4: v1(127,518) 161,552 161,656 174,669 200,669 206,663 206,645 190,629 190,603 197,596 210,596 257,643 262,643 269,650 269,674.75 240,703.75 240,736.31 213.31,763 107.31,763 82,788.31 82,853 145,916 178,916 196.85,934.85 pad.95@196.85,944.88
GPIOL3/K1: pad.97 U5.R1 | length 852
  Top1 w4: v1(148.07,234.8) U5.R1@160.87,222
  Signal2 w4: pad.97@118.11,944.88 118.11,890.11 108,880 79.31,880 32,832.69 32,338 95,275 134.69,275 148.07,261.62 v1(148.07,234.8)
GPIOL4/RECOVERY: pad.96 R23.1 U5.N2 | length 855.3
  Top1 w4: v1@173.96,260.5 v1(176.36,262.9) U5.N2@186.46,273
  Signal2 w4: pad.96@157.48,944.88 157.48,917.17 111.31,871 81.63,871 41,830.37 41,340.31 98.31,283 138,283 158.1,262.9 v1(176.36,262.9)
